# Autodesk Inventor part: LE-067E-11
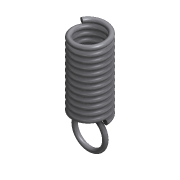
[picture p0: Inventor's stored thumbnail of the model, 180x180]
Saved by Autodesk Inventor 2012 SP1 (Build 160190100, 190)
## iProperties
Shininess: 0.0
Created: 2000-06
Part Number: LE-067E-11
Description: EXT. SPRG .50" OD X .067" X 4.50" LG
Vendor: LEE SPRINGS
Document SubType Name: Modeling
Designer: Ron
Material: Stainless Steel, Austenitic
Density: 1 g/cm^3
Density: 0.0
Volumn: 0.0
Area: 0.0
PropertySet Name: Model Information
Control State: 0
Master: False
Checked Out: False
Author: Ron
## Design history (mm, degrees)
node "Coil1" dims "d2" = 2.04216, "d3" = 25.4, "d4" = 10, "d5" = 0, "d6" = 90 deg, "d7" = 90 deg, "d8" = 0, "d9" = 0
  sketch "Sketch2"
    geometry: L1 (0, -27.602)-(0, 81.811) reference; L2 (-8.582, 0)-(8.982, 0) reference; C1 r 0.851 at (5.499, 0)
    constraints: 1 centre point, 1 point on line
    dimensions: "d0" = 5.4991 distance from line of L1 C1.centre (computed from d1); "d1" = 1.7018 diameter of C1
sketch "Sketch3"
  geometry: L1 (0, -28.684)-(0, 81.991) reference; L2 (0, -5.499)-(-4.762, -2.75); L3 (-9.834, 0)-(10.242, 0) reference; L4 (0, -5.499)-(0.675, -0.042); A1 r 5.499 centre (0, -5.499) between (-4.762, -2.75) and (0.675, -0.042)
  constraints: 4 end point, 2 point on circle, 1 centre point, 1 point on line
  dimensions: "d10" = 5.4991 radius of A1 (= d0); "d11" = 5.4991 distance from line of L3 L2.start (= d10); "d12" = 60 deg angle of L2 L1
workplane "Work Plane1"
node "Sweep1" dims "d14" = 0
  sketch "Sketch4"
    geometry: L1 (10.563, 0)-(-0.435, 0) reference; C1 r 0.851 at (0, 0); 2 further points
    constraints: 1 centre point, 1 coincident
    dimensions: "d13" = 1.7018 diameter of C1 (= d1)
sketch "Sketch5"
  geometry: L1 (0, -27.602)-(0, 81.811) reference; L2 (0, -10.02)-(0, 66.18); A1 r 4.727 centre (0, -5.499) between (-4.25, -3.429) and (0.249, -0.778) reference; 1 further point
  constraints: 3 point on line, 2 end point, 1 point on circle
  dimensions: "d15" = 76.2 distance of L2.start L2.end
workplane "Work Plane3"
node "Mirror1"
workaxis "Work Axis1"
body "Solid1"
other parameters: "d18" = 69.46695
